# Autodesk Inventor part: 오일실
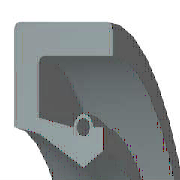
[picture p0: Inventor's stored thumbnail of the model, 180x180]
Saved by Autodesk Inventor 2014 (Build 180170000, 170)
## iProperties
IsCustomPart: 0
Company: 한국ATC센터
Created: 2014-08
Part Number: 오일실
Material: 고무
Description: 오일-실
Document SubType Name: Modeling
Standard: KS B 2804
Designer: KYOUNG IL JANG
Standards Organization: KS
Language: ko-KR
Size Designation: S - 17 30 8
Categories: <MemberInstance><Categories><Category DisplayName="샤프트 부품" InternalName="7f7aeb1f-a693-4053-b835-cee3144e0d98" Mnemonic="SHFT"><Category DisplayName="실링" Intern
Density: 0.93 g/cm^3
Appearance: 고무 - 검은색 - 버전 1.1
Mass: 1.6913 g
Surface Area: 28.0102 cm^2
Volume: 1.81861 cm^3
Author: KYOUNG IL JANG
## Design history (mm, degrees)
revolve "본체" stored, may be unused: angle "d17" = 90 deg
revolve "스프링1" stored, may be unused: angle "d18" = 90 deg
body "Solid1"
sketch "스케치1"
  geometry: L1 (0, 15)-(8, 15); L2 (8, 15)-(8, 13.75); L3 (8, 13.75)-(1.75, 13.75); L4 (0, 15)-(0, 10.6); L5 (0, 10.6)-(1.75, 10.25); L6 (1.75, 10.25)-(4.9, 8.5); L7 (4.9, 8.5)-(0, 8.5); L8 (6.3, 9.375)-(6.3, 10.6); L9 (0, 0)-(9.586, 0) reference; L10 (4.9, 8.5)-(6.3, 9.375); L11 (0, 18)-(0, -3) reference; L12 (-1.917, 0)-(11.503, 0) reference; L13 (4.2, 10.6)-(1.75, 11.09); L14 (1.75, 11.09)-(1.75, 13.75); L15 (6.3, 10.6)-(5.6, 10.6); C1 r 0.455 at (4.9, 10.6); A1 r 0.7 centre (4.9, 10.6) between (5.6, 10.6) and (4.2, 10.6)
  constraints: 26 end point, 5 horizontal alignment, 4 perpendicular, 2 centre point, 2 collinear, 2 horizontal, 2 parallel, 2 point on circle, 2 point on line, 2 vertical alignment, 1 coincident
  dimensions: "d0" = 30 diameter of L1 L9 (= SD2); "d1" = 18.75 diameter of L8.start L9 (= ABDM); "d2" = 1.25 distance of L1.end L2.end (computed from SD); "d3" = 0.91 diameter of C1 (= SPDI); "d4" = 1.4 diameter of A1 (= SPDA); "d5" = 17 diameter of L6.end L9 (= NND); "d6" = 20.5 diameter of L5.end L9 (= TKDM); "d7" = 21.2 diameter of L4.end L9 (= HLDM); "d8" = 4.9 distance from line of C1.centre L4 (= SPDST); "d9" = 6.3 distance between parallel lines of L8 L4 (= SDI); "d10" = 8 distance between parallel lines of L2 L4 (= SWDT); "d12" = 1.75 distance between parallel lines of L14 L4 (= SD)
fillet "모깎기1" dims "d11" = 0.3 (= RR)
other parameters: "SD2" = 30 [user parameter; used in 1 equation term], "SWDT" = 8 [user parameter; used in 1 equation term], "RR" = 0.3 [user parameter; used in 1 equation term], "SD" = 1.75 [user parameter; used in 2 equation terms], "NND" = 17 [user parameter; used in 1 equation term], "SPDA" = 1.4 [user parameter; used in 1 equation term], "SPDI" = 0.91 [user parameter; used in 1 equation term], "TKDM" = 20.5 [user parameter; used in 1 equation term], "HLDM" = 21.2 [user parameter; used in 1 equation term], "ABDM" = 18.75 [user parameter; used in 1 equation term], "SDI" = 6.3 [user parameter; used in 1 equation term], "SPDST" = 4.9 [user parameter; used in 1 equation term], "d13" = 0, "d14" = 0, "d15" = 0, "LAB" = 0.35 [user parameter]
